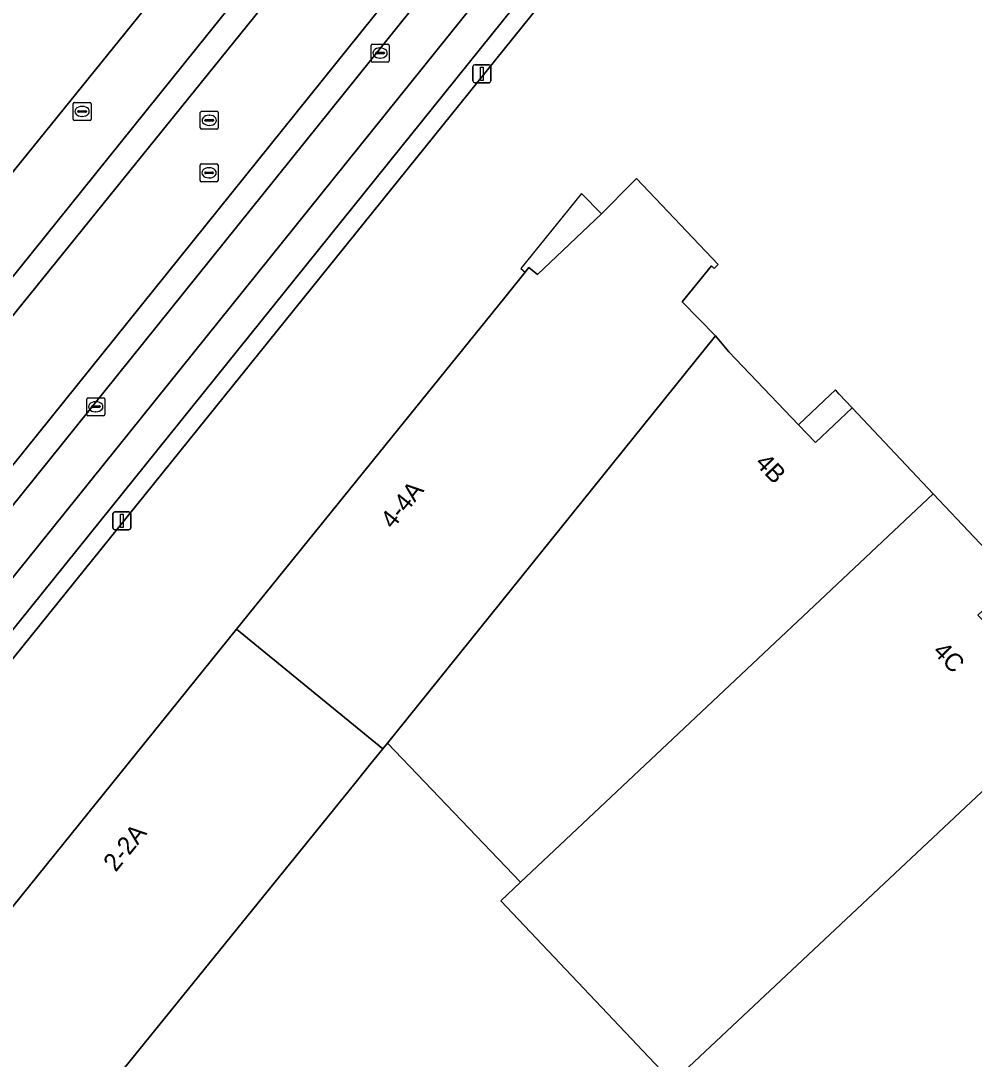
# Model space of a CAD drawing. Extents: x 156702 to 158052, y 387630 to 388992.
# Drawn here: x 157381.2 to 157434.2, y 388068.3 to 388126 of the extents above; entities that cross this region are included whole.
import ezdxf

# ---------------------------------------------------------------- set-up
doc = ezdxf.new("R2010")
doc.units = 0
for name, color, linetype in [('IMGEO_Brandkraan', 7, 'Continuous'), ('IMGEO_Erf', 7, 'Continuous'), ('IMGEO_Groenvoorziening', 7, 'Continuous'), ('IMGEO_Kolk', 7, 'Continuous'), ('IMGEO_Lichtmast', 7, 'Continuous'), ('IMGEO_Pand', 7, 'Continuous'), ('IMGEO_Pand_nummerreeks', 7, 'Continuous'), ('IMGEO_Pand_overbouw', 7, 'Continuous'), ('IMGEO_Parkeervlak_open', 7, 'Continuous'), ('IMGEO_Rijbaan_lokaal_gesloten', 7, 'Continuous'), ('IMGEO_Rijbaan_lokaal_open', 7, 'Continuous'), ('IMGEO_Rioolput', 7, 'Continuous'), ('IMGEO_Voetpad_open', 7, 'Continuous')]:
    doc.layers.add(name, color=color, linetype=linetype)

msp = doc.modelspace()

# ---------------------------------------------------------------- linework, layer by layer
at = {"layer": 'IMGEO_Brandkraan'}
for p, q in [((157384.198, 388121.478), (157385.05, 388121.478)), ((157384.123, 388120.552), (157384.123, 388121.404)), ((157384.382, 388120.972), (157384.382, 388120.984)), ((157384.82, 388120.935), (157384.422, 388120.935)), ((157384.425, 388121.021), (157384.823, 388121.021)), ((157384.611, 388121.258), (157384.636, 388121.258)), ((157384.866, 388120.984), (157384.866, 388120.972)), ((157385.124, 388121.404), (157385.124, 388120.552)), ((157385.05, 388120.478), (157384.198, 388120.478)), ((157384.634, 388120.698), (157384.609, 388120.698))]:
    msp.add_line(p, q, dxfattribs=at)
for points in [[(157384.198, 388121.478), (157385.05, 388121.478)], [(157384.123, 388120.552), (157384.123, 388121.404)], [(157385.124, 388121.404), (157385.124, 388120.552)], [(157385.05, 388120.478), (157384.198, 388120.478)]]:
    msp.add_lwpolyline(points, dxfattribs=at)
for centre, radius, start, end in [((157384.2, 388121.402), 0.0765, 91.55205, 178.44795), ((157384.2, 388121.402), 0.0765, 91.55205, 178.44795), ((157385.048, 388121.402), 0.0765, 1.55205, 88.44795), ((157385.048, 388121.402), 0.0765, 1.55205, 88.44795), ((157384.422, 388120.981), 0.0403, 85.87752, 175.75265), ((157384.419, 388120.971), 0.0366, 178.93798, 274.71019), ((157384.823, 388120.978), 0.043, 264.86636, 352.45326), ((157384.827, 388120.983), 0.0386, 1.73085, 96.63898), ((157384.2, 388120.554), 0.0765, 181.55205, 268.44795), ((157384.2, 388120.554), 0.0765, 181.55205, 268.44795), ((157385.048, 388120.554), 0.0765, 271.55205, 358.44795), ((157385.048, 388120.554), 0.0765, 271.55205, 358.44795)]:
    msp.add_arc(centre, radius, start, end, dxfattribs=at)
for centre, major_axis, ratio, start_param, end_param in [((157384.61, 388120.978), (-0.387, 0.002), 0.722429, 4.712389, 7.853982), ((157384.635, 388120.978), (-0.39, 0.002), 0.717154, 1.570796, 4.712389)]:
    msp.add_ellipse(centre, major_axis=major_axis, ratio=ratio, start_param=start_param, end_param=end_param, dxfattribs=at)
at = {"layer": 'IMGEO_Erf'}
for points in [[(157304.594, 388111.931), (157309.704, 388107.668), (157345.604, 388078.857), (157350.282, 388079.607), (157353.239, 388083.252), (157357.392, 388088.42), (157376.693, 388112.497), (157380.893, 388117.749), (157391.144, 388130.462), (157404.098, 388146.633), (157406.558, 388149.7), (157418.329, 388164.322), (157428.032, 388175.523), (157430.343, 388177.94), (157441.633, 388189.119), (157442.935, 388190.379), (157453.889, 388200.705), (157463.105, 388209.35), (157478.926, 388224.264), (157484.402, 388229.388), (157504.128, 388247.959), (157518.512, 388268.247), (157504.449, 388292.394)], [(157493.249, 388214.823), (157491.107, 388212.731), (157491.239, 388212.61), (157490.267, 388211.711), (157481.015, 388202.978), (157480.83, 388203.161), (157468.85, 388191.959), (157469.027, 388191.734), (157464.53, 388187.517), (157456.336, 388179.654), (157444.998, 388168.465), (157439.451, 388162.839), (157439.425, 388162.812), (157437.029, 388160.17), (157418.031, 388136.851), (157411.021, 388128.098), (157365.224, 388071.291), (157364.694, 388070.576)], [(157375.12, 388067.746), (157377.791, 388072.155), (157377.317, 388072.514), (157377.518, 388072.763), (157393.215, 388092.187), (157408.126, 388110.639), (157409.261, 388112.047), (157409.462, 388112.296), (157409.944, 388111.907), (157413.497, 388115.283), (157415.217, 388117.029), (157415.445, 388117.256), (157419.983, 388112.463), (157419.758, 388112.25), (157419.62, 388112.395), (157417.986, 388110.394), (157419.843, 388108.498), (157420.585, 388107.61), (157424.453, 388103.559), (157425.389, 388102.574), (157427.433, 388104.491), (157431.942, 388099.714), (157436.485, 388094.9)]]:
    msp.add_lwpolyline(points, dxfattribs=at)
at = {"layer": 'IMGEO_Groenvoorziening'}
msp.add_lwpolyline([(157365.224, 388071.291), (157411.021, 388128.098), (157410.172, 388128.763), (157409.295, 388127.628), (157364.459, 388071.912)], close=True, dxfattribs=at)
at = {"layer": 'IMGEO_Kolk'}
for p, q in [((157400.689, 388123.8), (157400.689, 388124.652)), ((157400.764, 388124.726), (157401.616, 388124.726)), ((157401.177, 388124.506), (157401.202, 388124.506)), ((157401.69, 388124.652), (157401.69, 388123.8)), ((157400.948, 388124.22), (157400.948, 388124.232)), ((157401.386, 388124.183), (157400.988, 388124.183)), ((157400.991, 388124.269), (157401.389, 388124.269)), ((157401.2, 388123.946), (157401.175, 388123.946)), ((157401.432, 388124.232), (157401.432, 388124.22)), ((157401.616, 388123.726), (157400.764, 388123.726)), ((157384.882, 388104.136), (157384.882, 388104.988)), ((157384.957, 388105.062), (157385.809, 388105.062)), ((157385.37, 388104.842), (157385.395, 388104.842)), ((157385.883, 388104.988), (157385.883, 388104.136)), ((157385.141, 388104.556), (157385.141, 388104.568)), ((157385.579, 388104.519), (157385.181, 388104.519)), ((157385.184, 388104.605), (157385.582, 388104.605)), ((157385.393, 388104.282), (157385.368, 388104.282)), ((157385.625, 388104.568), (157385.625, 388104.556)), ((157385.809, 388104.062), (157384.957, 388104.062))]:
    msp.add_line(p, q, dxfattribs=at)
for points in [[(157400.689, 388123.8), (157400.689, 388124.652)], [(157400.764, 388124.726), (157401.616, 388124.726)], [(157401.69, 388124.652), (157401.69, 388123.8)], [(157401.616, 388123.726), (157400.764, 388123.726)], [(157384.882, 388104.136), (157384.882, 388104.988)], [(157384.957, 388105.062), (157385.809, 388105.062)], [(157385.883, 388104.988), (157385.883, 388104.136)], [(157385.809, 388104.062), (157384.957, 388104.062)]]:
    msp.add_lwpolyline(points, dxfattribs=at)
for centre, radius, start, end in [((157400.766, 388124.65), 0.0765, 91.55205, 178.44795), ((157400.766, 388124.65), 0.0765, 91.55205, 178.44795), ((157401.614, 388124.65), 0.0765, 1.55205, 88.44795), ((157401.614, 388124.65), 0.0765, 1.55205, 88.44795), ((157400.766, 388123.802), 0.0765, 181.55205, 268.44795), ((157400.766, 388123.802), 0.0765, 181.55205, 268.44795), ((157400.988, 388124.229), 0.0403, 85.87752, 175.75265), ((157400.985, 388124.219), 0.0366, 178.93798, 274.71019), ((157401.389, 388124.226), 0.043, 264.86636, 352.45326), ((157401.393, 388124.231), 0.0386, 1.73085, 96.63898), ((157401.614, 388123.802), 0.0765, 271.55205, 358.44795), ((157401.614, 388123.802), 0.0765, 271.55205, 358.44795), ((157384.959, 388104.986), 0.0765, 91.55205, 178.44795), ((157384.959, 388104.986), 0.0765, 91.55205, 178.44795), ((157385.807, 388104.986), 0.0765, 1.55205, 88.44795), ((157385.807, 388104.986), 0.0765, 1.55205, 88.44795), ((157384.959, 388104.138), 0.0765, 181.55205, 268.44795), ((157384.959, 388104.138), 0.0765, 181.55205, 268.44795), ((157385.181, 388104.565), 0.0403, 85.87752, 175.75265), ((157385.178, 388104.555), 0.0366, 178.93798, 274.71019), ((157385.582, 388104.562), 0.043, 264.86636, 352.45326), ((157385.586, 388104.567), 0.0386, 1.73085, 96.63898), ((157385.807, 388104.138), 0.0765, 271.55205, 358.44795), ((157385.807, 388104.138), 0.0765, 271.55205, 358.44795)]:
    msp.add_arc(centre, radius, start, end, dxfattribs=at)
for centre, major_axis, ratio, start_param, end_param in [((157401.176, 388124.226), (-0.387, 0.002), 0.722429, 4.712389, 7.853982), ((157401.201, 388124.226), (-0.39, 0.002), 0.717154, 1.570796, 4.712389), ((157385.369, 388104.562), (-0.387, 0.002), 0.722429, 4.712389, 7.853982), ((157385.394, 388104.562), (-0.39, 0.002), 0.717154, 1.570796, 4.712389)]:
    msp.add_ellipse(centre, major_axis=major_axis, ratio=ratio, start_param=start_param, end_param=end_param, dxfattribs=at)
at = {"layer": 'IMGEO_Lichtmast'}
for p, q in [((157406.354, 388122.673), (157406.354, 388123.473)), ((157406.354, 388123.473), (157406.354, 388122.673)), ((157406.454, 388123.573), (157407.244, 388123.573)), ((157407.244, 388123.573), (157406.454, 388123.573)), ((157407.344, 388123.473), (157407.344, 388122.673)), ((157407.344, 388122.673), (157407.344, 388123.473)), ((157407.244, 388122.573), (157406.454, 388122.573)), ((157406.454, 388122.573), (157407.244, 388122.573)), ((157386.336, 388097.818), (157386.336, 388098.618)), ((157386.336, 388098.618), (157386.336, 388097.818)), ((157386.436, 388098.718), (157387.226, 388098.718)), ((157387.226, 388098.718), (157386.436, 388098.718)), ((157387.326, 388098.618), (157387.326, 388097.818)), ((157387.326, 388097.818), (157387.326, 388098.618)), ((157387.226, 388097.718), (157386.436, 388097.718)), ((157386.436, 388097.718), (157387.226, 388097.718))]:
    msp.add_line(p, q, dxfattribs=at)
for points in [[(157406.774, 388123.448), (157406.924, 388123.448), (157406.924, 388122.698), (157406.774, 388122.698), (157406.774, 388123.448)], [(157386.756, 388098.593), (157386.906, 388098.593), (157386.906, 388097.843), (157386.756, 388097.843), (157386.756, 388098.593)]]:
    msp.add_lwpolyline(points, dxfattribs=at)
for centre, start, end in [((157406.454, 388123.473), 90, 180), ((157406.454, 388123.473), 90, 180), ((157407.244, 388123.473), 0, 90), ((157407.244, 388123.473), 360, 90), ((157406.454, 388122.673), 180, 270), ((157406.454, 388122.673), 180, 270), ((157407.244, 388122.673), 270, 0), ((157407.244, 388122.673), 270, 0), ((157386.436, 388098.618), 90, 180), ((157386.436, 388098.618), 90, 180), ((157387.226, 388098.618), 0, 90), ((157387.226, 388098.618), 360, 90), ((157386.436, 388097.818), 180, 270), ((157386.436, 388097.818), 180, 270), ((157387.226, 388097.818), 270, 0), ((157387.226, 388097.818), 270, 0)]:
    msp.add_arc(centre, 0.1, start, end, dxfattribs=at)
at = {"layer": 'IMGEO_Pand'}
for points in [[(157401.351, 388085.55), (157401.597, 388085.854), (157419.843, 388108.498), (157417.986, 388110.394), (157419.62, 388112.395), (157419.758, 388112.25), (157419.983, 388112.463), (157415.445, 388117.256), (157415.217, 388117.029), (157413.497, 388115.283), (157409.944, 388111.907), (157409.462, 388112.296), (157409.261, 388112.047), (157408.126, 388110.639), (157393.215, 388092.187)], [(157408.998, 388078.123), (157431.942, 388099.714), (157427.433, 388104.491), (157425.389, 388102.574), (157424.453, 388103.559), (157420.585, 388107.61), (157419.843, 388108.498), (157401.597, 388085.854)], [(157439.457, 388087.676), (157435.374, 388092), (157434.424, 388092.98), (157436.485, 388094.9), (157431.942, 388099.714), (157408.998, 388078.123), (157407.904, 388077.089), (157417.44, 388067.002)], [(157401.351, 388085.55), (157393.215, 388092.187), (157377.518, 388072.763), (157377.317, 388072.514), (157377.791, 388072.155), (157375.12, 388067.746), (157373.801, 388065.569), (157373.516, 388065.423), (157378.044, 388060.636), (157378.275, 388060.85), (157378.097, 388061.046), (157379.662, 388063.087), (157381.537, 388061.074), (157399.778, 388083.607), (157400.684, 388084.726)], [(157439.457, 388087.676), (157417.44, 388067.002), (157427.052, 388056.836), (157434.011, 388049.475), (157435.268, 388050.312), (157428.151, 388057.872), (157451.075, 388079.489), (157446.532, 388084.275), (157444.494, 388082.34), (157443.551, 388083.339)], [(157401.351, 388085.55), (157400.684, 388084.726), (157399.778, 388083.607), (157381.537, 388061.074), (157385.632, 388056.676), (157386.548, 388055.693), (157384.534, 388053.774), (157392.75, 388045.095), (157398.472, 388050.495), (157399.125, 388049.804), (157409.662, 388059.698), (157413.562, 388063.36), (157417.44, 388067.002), (157407.904, 388077.089), (157408.998, 388078.123), (157401.597, 388085.854)]]:
    msp.add_lwpolyline(points, close=True, dxfattribs=at)
at = {"layer": 'IMGEO_Pand_overbouw'}
for points in [[(157409.261, 388112.047), (157409.462, 388112.296), (157409.944, 388111.907), (157413.497, 388115.283), (157412.394, 388116.418), (157409.015, 388112.247)], [(157424.453, 388103.559), (157425.389, 388102.574), (157427.433, 388104.491), (157426.711, 388105.267), (157426.502, 388105.493), (157425.867, 388104.903)]]:
    msp.add_lwpolyline(points, close=True, dxfattribs=at)
at = {"layer": 'IMGEO_Parkeervlak_open'}
for points in [[(157407.869, 388128.768), (157405.894, 388130.347), (157362.018, 388075.78)], [(157365.917, 388076.612), (157407.869, 388128.768)]]:
    msp.add_lwpolyline(points, dxfattribs=at)
at = {"layer": 'IMGEO_Rijbaan_lokaal_gesloten'}
for points in [[(157372.577, 388099.512), (157397.82, 388130.747), (157409.349, 388145.114), (157418.054, 388155.99), (157428.31, 388168.424), (157433.998, 388174.762), (157442.081, 388182.987), (157451.011, 388191.483), (157458.709, 388198.857), (157466.448, 388206.061), (157472.586, 388211.776), (157482.524, 388221.195), (157508.983, 388245.953), (157519.658, 388255.905)], [(157441.766, 388173.495), (157445.382, 388177.09), (157464.923, 388195.684), (157464.997, 388195.754), (157486.423, 388215.896), (157487.488, 388216.939), (157486.56, 388217.944), (157464.339, 388197.057), (157445.628, 388179.257), (157440.454, 388174.149), (157437.14, 388170.615), (157432.703, 388165.68), (157427.336, 388159.248), (157360.67, 388076.338), (157361.788, 388075.495), (157362.018, 388075.78), (157405.894, 388130.347)], [(157361.788, 388075.495), (157360.67, 388076.338), (157427.336, 388159.248), (157432.703, 388165.68), (157437.14, 388170.615), (157440.454, 388174.149), (157445.628, 388179.257), (157464.339, 388197.057), (157486.56, 388217.944)], [(157425.667, 388167.547), (157419.954, 388160.554), (157409.376, 388147.415), (157406.909, 388144.334), (157395.189, 388129.737), (157378.344, 388108.801), (157361.36, 388087.666), (157355.149, 388079.934), (157354.447, 388079.064)], [(157397.82, 388130.747), (157372.577, 388099.512), (157356.41, 388079.268), (157355.48, 388078.115), (157354.015, 388076.833), (157353.016, 388076.181), (157352.205, 388075.752), (157350.909, 388075.228), (157349.26, 388074.812), (157347.485, 388074.649), (157346.364, 388074.69), (157345.672, 388074.796), (157344.981, 388074.902), (157344.863, 388074.92), (157343.374, 388075.363), (157341.899, 388076.038), (157363.348, 388059.054)]]:
    msp.add_lwpolyline(points, dxfattribs=at)
at = {"layer": 'IMGEO_Rijbaan_lokaal_open'}
msp.add_lwpolyline([(157376.693, 388112.497), (157377.891, 388111.57), (157376.726, 388110.062), (157378.344, 388108.801), (157395.189, 388129.737), (157393.555, 388130.997), (157392.39, 388129.493), (157391.144, 388130.462), (157380.893, 388117.749)], close=True, dxfattribs=at)
at = {"layer": 'IMGEO_Rioolput'}
for p, q in [((157391.193, 388120.058), (157391.193, 388120.91)), ((157391.268, 388120.984), (157392.12, 388120.984)), ((157392.194, 388120.91), (157392.194, 388120.058)), ((157391.452, 388120.478), (157391.452, 388120.49)), ((157391.89, 388120.441), (157391.492, 388120.441)), ((157391.495, 388120.527), (157391.893, 388120.527)), ((157391.681, 388120.764), (157391.706, 388120.764)), ((157391.936, 388120.49), (157391.936, 388120.478)), ((157392.12, 388119.984), (157391.268, 388119.984)), ((157391.704, 388120.204), (157391.679, 388120.204)), ((157391.18, 388117.14), (157391.18, 388117.992)), ((157391.255, 388118.066), (157392.107, 388118.066)), ((157392.181, 388117.992), (157392.181, 388117.14)), ((157391.439, 388117.56), (157391.439, 388117.572)), ((157391.877, 388117.523), (157391.479, 388117.523)), ((157391.482, 388117.609), (157391.88, 388117.609)), ((157391.668, 388117.846), (157391.693, 388117.846)), ((157391.923, 388117.572), (157391.923, 388117.56)), ((157392.107, 388117.066), (157391.255, 388117.066)), ((157391.691, 388117.286), (157391.666, 388117.286))]:
    msp.add_line(p, q, dxfattribs=at)
for points in [[(157391.193, 388120.058), (157391.193, 388120.91)], [(157391.268, 388120.984), (157392.12, 388120.984)], [(157392.194, 388120.91), (157392.194, 388120.058)], [(157392.12, 388119.984), (157391.268, 388119.984)], [(157391.18, 388117.14), (157391.18, 388117.992)], [(157391.255, 388118.066), (157392.107, 388118.066)], [(157392.181, 388117.992), (157392.181, 388117.14)], [(157392.107, 388117.066), (157391.255, 388117.066)]]:
    msp.add_lwpolyline(points, dxfattribs=at)
for centre, radius, start, end in [((157391.27, 388120.908), 0.0765, 91.55205, 178.44795), ((157391.27, 388120.908), 0.0765, 91.55205, 178.44795), ((157392.118, 388120.908), 0.0765, 1.55205, 88.44795), ((157392.118, 388120.908), 0.0765, 1.55205, 88.44795), ((157391.492, 388120.487), 0.0403, 85.87752, 175.75265), ((157391.489, 388120.477), 0.0366, 178.93798, 274.71019), ((157391.893, 388120.484), 0.043, 264.86636, 352.45326), ((157391.897, 388120.489), 0.0386, 1.73085, 96.63898), ((157391.27, 388120.06), 0.0765, 181.55205, 268.44795), ((157391.27, 388120.06), 0.0765, 181.55205, 268.44795), ((157392.118, 388120.06), 0.0765, 271.55205, 358.44795), ((157392.118, 388120.06), 0.0765, 271.55205, 358.44795), ((157391.257, 388117.99), 0.0765, 91.55205, 178.44795), ((157391.257, 388117.99), 0.0765, 91.55205, 178.44795), ((157392.105, 388117.99), 0.0765, 1.55205, 88.44795), ((157392.105, 388117.99), 0.0765, 1.55205, 88.44795), ((157391.479, 388117.569), 0.0403, 85.87752, 175.75265), ((157391.476, 388117.559), 0.0366, 178.93798, 274.71019), ((157391.88, 388117.566), 0.043, 264.86636, 352.45326), ((157391.884, 388117.571), 0.0386, 1.73085, 96.63898), ((157391.257, 388117.142), 0.0765, 181.55205, 268.44795), ((157391.257, 388117.142), 0.0765, 181.55205, 268.44795), ((157392.105, 388117.142), 0.0765, 271.55205, 358.44795), ((157392.105, 388117.142), 0.0765, 271.55205, 358.44795)]:
    msp.add_arc(centre, radius, start, end, dxfattribs=at)
for centre, major_axis, ratio, start_param, end_param in [((157391.68, 388120.484), (-0.387, 0.002), 0.722429, 4.712389, 7.853982), ((157391.705, 388120.484), (-0.39, 0.002), 0.717154, 1.570796, 4.712389), ((157391.667, 388117.566), (-0.387, 0.002), 0.722429, 4.712389, 7.853982), ((157391.692, 388117.566), (-0.39, 0.002), 0.717154, 1.570796, 4.712389)]:
    msp.add_ellipse(centre, major_axis=major_axis, ratio=ratio, start_param=start_param, end_param=end_param, dxfattribs=at)
at = {"layer": 'IMGEO_Voetpad_open'}
msp.add_lwpolyline([(157364.694, 388070.576), (157365.224, 388071.291), (157364.459, 388071.912), (157409.295, 388127.628), (157407.869, 388128.768), (157365.917, 388076.612)], dxfattribs=at)

# ---------------------------------------------------------------- texts
at = {"layer": 'IMGEO_Pand_nummerreeks'}
for s, rotation, p in [('4B', 313.53884, (157421.99, 388101.39)), ('4-4A', 51.05844, (157401.899, 388097.715)), ('4C', 314.10946, (157431.865, 388090.907)), ('2-2A', 51.05788, (157386.495, 388078.653))]:
    msp.add_text(s, height=1, rotation=rotation, dxfattribs=at).set_placement(p)

doc.saveas('drawing.dxf')
